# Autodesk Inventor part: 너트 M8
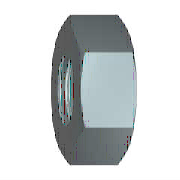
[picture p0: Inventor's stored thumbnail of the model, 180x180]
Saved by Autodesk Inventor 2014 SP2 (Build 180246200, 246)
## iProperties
IsCustomPart: 1
Created: 2012-02
Part Number: 너트 M8
Material: 강철, 연강
Description: 6각 너트 및 6각 가는 너트
Document SubType Name: Modeling
Standard: KS B 1012
Designer: mduedu
Standards Organization: KS
Language: ko-KR
Size Designation: M 8
Categories: <MemberInstance><Categories><Category DisplayName="조임쇠" InternalName="e4da775c-781d-43d5-af7c-5136215cf5a6" Mnemonic="FSTN"><Category DisplayName="너트" InternalN
Density: 1 g/cm^3
Appearance: 강철
Author: mduedu
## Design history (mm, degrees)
sketch "스케치1"
  geometry: L1 (-7.506, 0)-(-3.753, 6.5); L2 (-3.753, 6.5)-(3.753, 6.5); L3 (3.753, 6.5)-(7.506, 0); L4 (7.506, 0)-(3.753, -6.5); L5 (3.753, -6.5)-(-3.753, -6.5); L6 (-3.753, -6.5)-(-7.506, 0); 2 further points
  constraints: 12 end point, 1 coincident, 1 horizontal, 11 other
  dimensions: "d0" = 15.01111 distance of L3.end L1.start (= 1.1547 x SW)
extrude "본체" new body sketch "스케치1" distance "d1" = 5 (= KOH); taper "d2" = 0 deg
sketch "스케치2"
  geometry: L1 (0, 3.753)-(0, 7.506) reference; L2 (0, 7.506)-(5, 7.506) reference; L3 (5, 3.753)-(5, 7.506) reference; L4 (-1, 0)-(6, 0) reference; L5 (0.581, 7.506)-(0, 6.5); L6 (4.419, 7.506)-(5, 6.5)
  constraints: 4 end point, 4 point on line
  dimensions: "d3" = 30 deg angle of L1 L5 (= ANG1); "d4" = 30 deg angle of L3 L6 (= ANG2); "d5" = 13 diameter of L5.end L4 (= SW0); "d6" = 13 diameter of L6.end L4 (= SW01)
revolve "모따기1" sketch "스케치2" stored, may be unused: angle "d7" = 90 deg
sketch "스케치3"
  geometry: A1 r 6.5 centre (0, 0) between (-3.25, -5.629) and (3.25, -5.629) reference; 1 further point
  constraints: 1 coincident
hole "스레드" sketch "스케치3" at (0, 0) diameter "d25" = 6.647; stored, may be unused: countersink angle "d29" = 82 deg, drill point angle "d31" = 118 deg; dims "d26" = 6, "d27" = 4, "d28" = 2, "d30" = 8
workaxis "Work Axis1"
workplane "Work Plane1"
body "Solid1"
chamfer "모따기2" distance "d8" = 0.67658 (= -0.5 x GD1 + 0.5 x NND); stored, may be unused: angle "d9" = 30 deg, second distance "d40" = 0.67658 (= -0.5 x GD1 + 0.5 x NND)
chamfer "모따기3" distance "d10" = 0.67658 (= -0.5 x GD1 + 0.5 x NND); stored, may be unused: angle "d11" = 30 deg, second distance "d41" = 0.67658 (= -0.5 x GD1 + 0.5 x NND)
other parameters: "ANG1" = 30 deg [user parameter; used in 1 equation term], "ANG2" = 30 deg [user parameter; used in 1 equation term], "NND" = 8 [user parameter; used in 4 equation terms], "KOH" = 5 [user parameter; used in 1 equation term], "SW" = 13 [user parameter; used in 4 equation terms], "SW0" = 13 (= SW) [user parameter; used in 1 equation term], "SW01" = 13 (= SW) [user parameter; used in 1 equation term], "GD1" = 6.64684 (computed from THREADDIA, PTC, TOA) [user parameter; used in 4 equation terms], "d13" = 0, "d14" = 0, "d39" = 0, "d42" = 0, "GUL" = 0.67658 (= 0.541266 x PTC) [user parameter], "TPU" = 8 (computed from PTC) [user parameter], "THREADDIA" = 8 [user parameter; used in 1 equation term], "TOA" = 30 deg [user parameter; used in 1 equation term], "PTC" = 1.25 [user parameter; used in 4 equation terms], "E0" = 15.015 (= 1.155 x SW) [user parameter], "GAL" = 0.67658 (= 0.541266 x PTC) [user parameter]
